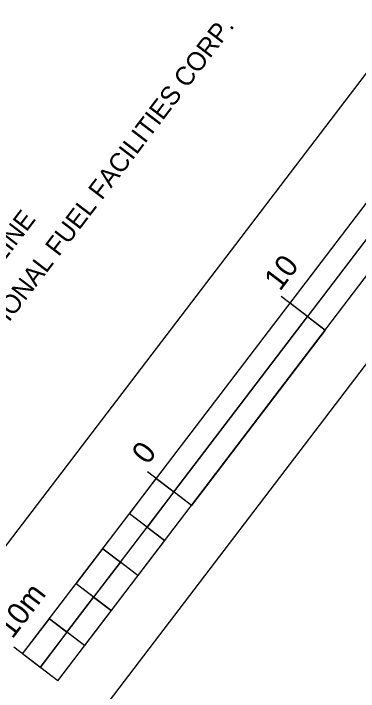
# Model space of a CAD drawing. Extents: x 599744 to 600217, y 4827560 to 4828065.
# Drawn here: x 600131.6 to 600147.25, y 4827872.06 to 4827902.8 of the extents above; entities that cross this region are included whole.
import ezdxf

# ---------------------------------------------------------------- set-up
doc = ezdxf.new("R2010")
doc.units = 0
for name, color, linetype in [('G-ANNO-BAR', 7, 'Continuous'), ('G-ANNO-TEXT', 7, 'Continuous'), ('G-TTLB-OTLN', 7, 'Continuous')]:
    doc.layers.add(name, color=color, linetype=linetype)

msp = doc.modelspace()

# ---------------------------------------------------------------- linework, layer by layer
at = {"layer": 'G-ANNO-BAR'}
for p, q in [((600132.013, 4827873.761), (600156.275, 4827905.563)), ((600132.808, 4827873.154), (600157.07, 4827904.956)), ((600133.603, 4827872.547), (600157.865, 4827904.35)), ((600145.734, 4827888.449), (600143.747, 4827889.965)), ((600139.669, 4827880.498), (600137.681, 4827882.014)), ((600138.456, 4827878.908), (600136.866, 4827880.121)), ((600137.243, 4827877.318), (600135.652, 4827878.531)), ((600136.029, 4827875.728), (600134.439, 4827876.941)), ((600134.816, 4827874.138), (600133.226, 4827875.351)), ((600133.603, 4827872.547), (600131.616, 4827874.064))]:
    msp.add_line(p, q, dxfattribs=at)
for points in [[(600144.144, 4827889.662), (600150.209, 4827897.612), (600151.004, 4827897.006), (600144.939, 4827889.055)], [(600138.874, 4827881.105), (600144.939, 4827889.055), (600145.734, 4827888.449), (600139.669, 4827880.498)], [(600136.866, 4827880.121), (600138.079, 4827881.711), (600138.874, 4827881.105), (600137.661, 4827879.514)], [(600136.448, 4827877.924), (600137.661, 4827879.514), (600138.456, 4827878.908), (600137.243, 4827877.318)], [(600134.439, 4827876.941), (600135.652, 4827878.531), (600136.448, 4827877.924), (600135.234, 4827876.334)], [(600134.021, 4827874.744), (600135.234, 4827876.334), (600136.029, 4827875.728), (600134.816, 4827874.138)], [(600132.013, 4827873.761), (600133.226, 4827875.351), (600134.021, 4827874.744), (600132.808, 4827873.154)]]:
    msp.add_lwpolyline(points, close=True, dxfattribs=at)
at = {"layer": 'G-TTLB-OTLN'}
for p, q in [((600166.482, 4827924.86), (600128.027, 4827874.452)), ((600172.843, 4827920.007), (600134.387, 4827869.6))]:
    msp.add_line(p, q, dxfattribs=at)

# ---------------------------------------------------------------- texts
at = {"layer": 'G-ANNO-BAR'}
for s, p in [('10', (600143.687, 4827890.176)), ('0', (600137.682, 4827882.301)), ('10m', (600131.544, 4827874.406))]:
    msp.add_text(s, height=1, rotation=52.6603, dxfattribs=at).set_placement(p)
at = {"layer": 'G-ANNO-TEXT'}
for s, height, p in [('48 HOURS PRIOR TO COMMENCING WORK NOTIFY THE FOLLOWING', 1.25, (600107.401, 4827892.497)), ('PEARSON INTERNATIONAL FUEL FACILITIES CORP.', 0.85, (600124.38, 4827879.591)), ('TRANS NORTHERN PIPELINE', 0.85, (600122.909, 4827880.713))]:
    msp.add_text(s, height=height, rotation=52.6603, dxfattribs=at).set_placement(p)

doc.saveas('drawing.dxf')
